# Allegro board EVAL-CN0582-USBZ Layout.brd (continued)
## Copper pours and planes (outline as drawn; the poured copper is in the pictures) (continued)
5V_USB on L3_SIG: 8.51,42.93 8.51,40.77 9.78,40.77 9.78,42.93
26V8_SUPPLY on TOP: 23.75,72.52 24,72.26 26.29,72.26 26.54,72.52 26.54,78.87 26.42,78.99 23.88,78.99 23.75,78.87
26V_SUPPLY on TOP (solid shape): 96.14,60.74 96.14,58.97 96.01,58.85 92.46,58.85 92.33,58.97 92.33,60.74 92.46,60.86 96.01,60.86
26V_SUPPLY on TOP (solid shape): 96.14,22.23 96.14,20.46 96.01,20.34 92.46,20.34 92.33,20.46 92.33,22.23 92.46,22.35 96.01,22.35
26V_SUPPLY on TOP (solid shape): 92.76,68.97 92.81,68.97 93.44,68.97 93.48,68.97 93.53,68.99 96.14,68.99 96.27,68.86 96.27,67.23 96.14,67.1 92.58,67.1 92.46,67.23 92.46,68.86 92.58,68.99 92.71,68.99
26V_SUPPLY on TOP (solid shape): 92.76,30.46 92.81,30.46 93.44,30.46 93.48,30.46 93.53,30.48 96.14,30.48 96.27,30.35 96.27,28.72 96.14,28.59 92.58,28.59 92.46,28.72 92.46,30.35 92.58,30.48 92.71,30.48
26V_SUPPLY on TOP: 32,75.56 32,73.15 31.5,72.64 30.61,72.64 29.34,71.37 27.81,71.37 27.69,71.5 27.69,74.55 27.81,74.68 31.5,74.68 31.75,74.93 31.75,75.56
26V_SUPPLY on L4_SIG: 38.61,79.76 70.1,79.76 70.1,73.91 70.18,73.73 70.36,73.66 106.43,73.66 106.43,10.92 88.9,10.92 88.9,14.48 92.33,14.48 92.51,14.55 92.58,14.73 92.58,31.88 92.51,32.06 92.33,32.13 89.15,32.13 89.15,35.56 92.33,35.56 92.51,35.63 92.58,35.81 92.58,49.28 92.51,49.46 92.33,49.53 89.03,49.53 89.03,53.09 92.33,53.09 92.51,53.16 92.58,53.34 92.58,64.39 92.51,64.57 92.33,64.64 62.99,64.64 62.99,74.42 62.92,74.6 62.74,74.68 45.09,74.68 44.91,74.6 44.83,74.42 44.83,70.99 26.42,70.99 26.42,74.8 38.35,74.8 38.53,74.88 38.61,75.06
DGND on TOP: 33.27,76.83 31.11,76.83 30.99,76.96 29.84,76.96 29.59,77.22 29.59,78.74 26.92,78.74 26.8,78.61 26.8,75.31 26.92,75.18 30.48,75.18 31.11,75.82 33.27,75.82
DGND on TOP: 10.16,45.47 10.03,45.34 6.98,45.34 6.6,44.96 6.6,39.75 6.48,39.62 3.94,39.62 3.81,39.75 3.81,40.51 4.45,41.15 4.45,43.18 4.19,43.43 0.89,43.43 0.89,51.56 1.14,51.82 6.48,51.82 8.26,53.59 10.03,53.59 10.16,53.47
DGND on BOTTOM: 0.76,103.76 118.74,103.76 118.74,0.64 0.76,0.64 ; 5 cut-outs
DGND on L2_GND, L5_GND: 0.76,103.76 118.74,103.76 118.74,0.64 0.76,0.64
DGND on L3_SIG: 0.76,103.76 118.74,103.76 118.74,0.64 0.76,0.64
P5V_SUPPLY on TOP: 53.09,102.36 53.09,99.95 53.21,99.82 55.25,99.82 55.37,99.95 55.37,102.36 55.25,102.49 53.21,102.49
P5V_SUPPLY on L3_SIG: 53.85,102.36 53.85,100.97 55.37,100.97 55.37,102.36
P5V_SUPPLY on L4_SIG: 40.39,103.76 118.74,103.76 118.74,88.9 98.55,88.9 98.55,96.27 98.48,96.45 98.3,96.52 70.48,96.52 70.31,96.45 70.23,96.27 70.23,92.58 70.31,92.4 70.48,92.33 71.37,92.33 71.37,89.53 40.39,89.53
V1P2_SUPPLY on TOP: 29.13,14.99 29.13,14.17 30.3,13 30.3,11.63 30.38,11.56 32.23,11.56 32.31,11.63 32.31,14.35 32.05,14.6 30.1,14.6 29.72,14.99
V1P2_SUPPLY on L4_SIG: 35.16,27.69 50.31,27.69 51.05,26.95 51.05,23.24 51.07,23.14 51.13,23.06 53.09,21.1 53.09,12.81 52.09,11.81 30.73,11.81 30.73,22.61 34.04,22.61 34.22,22.68 34.29,22.86 34.29,26.82
(no net) on TOP: 89.53,59.2 89.53,56.28 89.66,56.15 91.82,56.15 91.95,56.28 91.95,59.07 91.82,59.2
(no net) on TOP: 89.66,80.15 89.66,77.23 89.79,77.1 91.95,77.1 92.08,77.23 92.08,80.03 91.95,80.15
(no net) on TOP: 74.55,74.18 73.41,74.18 73.15,74.44 73.15,77.74 73.28,77.87 74.42,77.87 74.68,77.61 74.68,74.31
(no net) on TOP: 89.66,41.64 89.66,38.72 89.79,38.59 91.95,38.59 92.08,38.72 92.08,41.51 91.95,41.64
(no net) on TOP: outline of 118 points within 0.76,0.63 118.75,103.76 ; 18 cut-outs
(no net) on TOP: 96.27,67.23 96.27,68.86 96.14,68.99 92.58,68.99 92.46,68.86 92.46,67.23 92.58,67.1 96.14,67.1
(no net) on TOP: 96.14,20.46 96.14,22.23 96.01,22.35 92.46,22.35 92.33,22.23 92.33,20.46 92.46,20.34 96.01,20.34
(no net) on TOP: 97.54,66.44 97.54,64.53 97.79,64.28 97.79,63.4 97.66,63.28 93.73,63.28 93.6,63.4 93.6,66.56 97.41,66.56
(no net) on TOP: 74.55,35.67 73.41,35.67 73.15,35.93 73.15,39.23 73.28,39.35 74.42,39.35 74.68,39.1 74.68,35.8
(no net) on TOP: 74.42,53.23 73.28,53.23 73.03,53.48 73.03,56.78 73.15,56.91 74.3,56.91 74.55,56.66 74.55,53.36
(no net) on TOP: 74.42,14.72 73.28,14.72 73.03,14.97 73.03,18.27 73.15,18.4 74.3,18.4 74.55,18.15 74.55,14.84
(no net) on TOP: 97.54,27.92 97.54,26.02 97.79,25.76 97.79,24.89 97.66,24.77 93.73,24.77 93.6,24.89 93.6,28.05 97.41,28.05
(no net) on TOP: 96.14,58.97 96.14,60.74 96.01,60.86 92.46,60.86 92.33,60.74 92.33,58.97 92.46,58.85 96.01,58.85
(no net) on TOP: 97.41,58.18 97.41,56.28 97.66,56.02 97.66,55.15 97.54,55.02 93.6,55.02 93.47,55.15 93.47,58.31 97.28,58.31
(no net) on TOP: 97.41,19.67 97.41,17.76 97.66,17.51 97.66,16.64 97.54,16.51 93.6,16.51 93.47,16.64 93.47,19.8 97.28,19.8
(no net) on TOP: 96.27,28.72 96.27,30.35 96.14,30.48 92.58,30.48 92.46,30.35 92.46,28.72 92.58,28.59 96.14,28.59
(no net) on TOP: 89.53,20.69 89.53,17.76 89.66,17.64 91.82,17.64 91.95,17.76 91.95,20.56 91.82,20.69
3P3V_SUPPLY on TOP: 57.91,29.97 57.91,25.02 57.66,24.77 56.26,24.77 56.01,25.02 56.01,29.85 56.13,29.97
3P3V_SUPPLY on TOP: 17.14,18.41 17.14,18.67 17.4,18.92 17.4,22.48 17.27,22.61 13.08,22.61 12.45,21.97 12.45,18.67 12.7,18.41
3P3V_SUPPLY on L3_SIG: 51.18,20.96 51.18,17.27 47.88,13.97 40.39,13.97 40.13,14.22 40.13,20.45 40.39,20.7 42.29,20.7 44.01,22.42 44.01,26.99 44.45,27.43 49.28,27.43 51.69,25.02 51.69,21.46
3P3V_SUPPLY on L4_SIG: 0.76,103.76 39.88,103.76 39.88,89.28 39.95,89.1 40.13,89.03 69.34,89.03 69.34,80.26 38.35,80.26 38.17,80.19 38.1,80.01 38.1,75.31 31.37,75.31 31.37,87.5 31.35,87.6 31.29,87.68 31.04,87.94 30.96,87.99 30.86,88.01 22.86,88.01 22.76,87.99 22.68,87.94 13.92,79.17 13.86,79.09 13.84,78.99 13.84,36.96 13.08,36.96 12.9,36.88 12.83,36.7 12.83,30.73 12.9,30.55 13.08,30.48 15.77,30.48 18.16,28.09 18.16,18.92 17.14,18.92 16.97,18.85 16.89,18.67 16.89,16 15.62,16 15.44,15.93 15.37,15.75 15.37,13.59 15.44,13.41 15.62,13.33 19.3,13.33 19.48,13.41 19.56,13.59 19.56,14.86 26.16,14.86 26.34,14.93 26.42,15.11 26.42,70.48 45.09,70.48 45.26,70.56 45.34,70.74 45.34,74.17 48.01,74.17 48.01,62.1 42.55,62.1 42.37,62.03 42.29,61.85 42.29,58.42 42.31,58.32 42.37,58.24 44.14,56.46 44.23,56.41 44.32,56.39 62.48,56.39 62.48,43.56 62.56,43.38 62.74,43.31 71.5,43.31 71.5,31.62 59.56,31.62 59.38,31.55 59.31,31.37 59.31,0.64 0.76,0.64 ; 1 cut-out
10P5V_SUPPLY on TOP: 36.83,102.23 36.83,99.69 37.21,99.31 39.88,99.31 39.88,102.23 39.75,102.36 36.96,102.36
-10P5_SUPPLY on TOP: 43.56,90.68 43.56,87.63 43.31,87.38 41.02,87.38 40.77,87.63 40.77,90.68 40.89,90.8 43.43,90.8
CON_VBUS on TOP: 6.73,39.37 6.73,37.46 3.94,37.46 3.81,37.59 3.81,39.37
CON_VBUS on L3_SIG: 3.84,39.27 3.84,29.95 4.22,29.57 10.9,29.57 11.07,29.74 11.07,32.64 10.72,32.99 10.72,39.27 10.62,39.37 3.94,39.37
N5V_SUPPLY on TOP: 53.47,89.74 53.47,87.99 53.54,87.91 55.35,87.91 55.47,88.04 55.47,89.71 55.4,89.79 53.52,89.79
N5V_SUPPLY on BOTTOM: 53.75,95.91 53.75,87.88 54.13,87.5 90.42,87.5 92.08,89.15 102.9,89.15 103.15,89.41 103.15,96.06 99.11,96.06 99.09,96.04 95.1,100.03 57.86,100.03
N5V_SUPPLY on L3_SIG: 101.22,90.68 96.65,90.68 96.27,90.3 96.27,83.19 98.93,80.52 98.93,14.86 99.31,14.48 101.35,14.48 101.47,14.6 101.47,90.42
SYS_POWER on TOP: 29.34,90.93 29.34,84.71 29.46,84.58 31.88,84.58 32.13,84.84 32.13,87.25 31.11,88.27 31.11,88.52 30.73,88.9 30.73,90.93
SYS_POWER on TOP: 16.89,74.17 16.89,69.22 16.64,68.96 13.84,68.96 13.72,69.09 13.72,74.04 13.84,74.17
SYS_POWER on TOP: 22.99,63.25 25.78,63.25 26.04,63.5 26.92,63.5 26.92,64.64 25.02,64.64 24.64,64.26 22.99,64.26
SYS_POWER on TOP: 16,16.51 16,14.73 16.13,14.6 18.92,14.6 19.18,14.86 19.18,16.64 16.13,16.64
SYS_POWER on TOP: 18.54,77.22 18.29,77.22 18.29,78.87 18.03,79.12 18.03,80.52 18.16,80.64 19.18,80.64 19.3,80.52 19.3,78.99 18.54,78.23
SYS_POWER on TOP: 21.72,42.16 21.72,38.99 24.51,38.99 25.02,39.5 25.02,41.66 24.51,42.16
SYS_POWER on L4_SIG: 22.97,87.5 30.76,87.5 30.86,87.4 30.86,75.31 26.16,75.31 25.98,75.24 25.91,75.06 25.91,15.37 19.3,15.37 19.12,15.29 19.05,15.11 19.05,13.84 15.88,13.84 15.88,15.49 17.14,15.49 17.32,15.57 17.4,15.75 17.4,18.41 18.41,18.41 18.59,18.49 18.67,18.67 18.67,28.19 18.65,28.29 18.59,28.37 16.05,30.91 15.97,30.97 15.88,30.99 13.34,30.99 13.34,36.45 14.1,36.45 14.28,36.52 14.35,36.7 14.35,78.89
UNNAMED_22_ADP5071V2_I1_INBK on TOP: 29.97,95.88 29.97,96.9 28.32,98.55 28.32,101.98 28.45,102.11 29.84,102.11 29.97,101.98 29.97,97.66 30.35,97.28 30.35,95.88
UNNAMED_22_ADP5071V2_I1_SW1 on TOP: 30.61,95.63 30.61,101.85 30.86,102.11 34.8,102.11 34.8,98.17 34.42,97.79 31.5,97.79 31.11,97.41 31.11,95.63
UNNAMED_22_ADP5071V2_I1_SW2 on TOP: 31.24,91.06 31.24,89.15 31.75,88.65 38.35,88.65 38.61,88.9 38.61,90.55 38.1,91.06
UNNAMED_22_ADP7118V2_I56_VIN on TOP: 47.75,99.82 43.82,99.82 43.69,99.69 42.04,99.69 41.78,99.44 40.51,99.44 40.51,102.36 40.64,102.49 47.62,102.49 47.75,102.36
UNNAMED_22_ADP7118V2_I56_VOUT on TOP: 48.39,102.36 48.39,99.95 48.51,99.82 52.45,99.82 52.58,99.95 52.58,102.23 52.32,102.49 48.51,102.49
UNNAMED_22_ADP7182V5_I66_EPAD on TOP: 48.01,90.68 44.45,90.68 44.32,90.55 44.32,87.76 44.45,87.63 47.62,87.63 47.75,87.76 47.75,89.53 47.88,89.66 49.15,89.66 49.28,89.79 49.28,93.85 49.02,94.11 48.26,94.11 48.13,93.98 48.13,90.8
UNNAMED_22_ADP7182V5_I66_VOUT on TOP: 49.66,90.68 49.66,90.42 49.78,90.42 49.91,90.3 49.91,87 50.16,86.74 52.58,86.74 52.96,87.12 52.96,90.55 52.83,90.68
UNNAMED_22_CAP_I337_N1 on TOP: 0.89,42.93 3.94,42.93 3.94,41.4 3.3,40.77 3.3,36.32 3.05,36.07 2.67,36.07 2.67,28.32 2.92,28.07 8.13,28.07 8.13,25.53 7.75,25.15 0.89,25.15 0.76,25.27 0.76,42.8
UNNAMED_22_CAP_I337_N1 on BOTTOM: 0.89,38.35 9.53,38.35 9.53,26.42 0.89,26.42
UNNAMED_23_ADP1708_I291_OUT on TOP: 14.35,17.91 14.35,16.38 13.97,16 13.97,14.6 13.08,14.6 12.57,14.1 11.43,14.1 11.18,14.35 11.18,17.53 11.56,17.91
UNNAMED_23_ADP7118V2_I83_EN on TOP: 31.88,64.77 31.88,60.2 31.24,59.56 29.08,59.56 28.83,59.31 28.83,58.29 29.21,57.91 33.02,57.91 33.02,58.42 34.16,59.56 34.16,64.64 34.04,64.77
UNNAMED_23_ADP7118V2_I83_VOUT on TOP: 33.91,58.8 33.91,57.91 34.04,57.78 37.08,57.78 37.21,57.66 38.23,57.66 38.23,58.42 38.1,58.55 37.47,58.55 37.08,58.93 34.04,58.93
UNNAMED_23_ADP7142_I123_EN on TOP: 32,77.09 31.62,77.09 31.24,77.47 30.23,77.47 30.1,77.6 30.1,79.12 29.84,79.38 23.75,79.38 23.49,79.63 23.49,80.64 23.62,80.77 31.62,80.77 32,80.39
UNNAMED_23_CAP_I54_N1 on TOP: 18.59,64.24 18.59,63.22 15.49,63.22 15.01,62.74 11.15,62.74 11.1,62.79 11.1,64.08 11.25,64.24
UNNAMED_23_CAP_I54_N2 on TOP: 18.59,62.92 15.8,62.92 15.75,62.86 15.75,62.31 17.07,62.31 17.32,62.56 18.59,62.56
UNNAMED_23_CAP_I55_N1 on TOP: 18.59,65.18 17.14,65.18 16.84,65.48 11.15,65.48 11.13,65.46 11.13,66.75 11.2,66.83 16.43,66.83 17.09,66.17 18.59,66.17
UNNAMED_23_CAP_I55_N2 on TOP: 18.54,64.52 15.82,64.52 15.82,65.1 16.81,65.1 17.04,64.87 18.57,64.87 18.57,64.54
UNNAMED_23_CAP_I63_N2 on TOP: 22.99,65.79 24.64,65.79 25.15,65.28 33.4,65.28 33.4,66.8 33.27,66.93 25.27,66.93 24.51,66.17 22.99,66.17
UNNAMED_23_CAP_I241_N2 on TOP: 13.72,56.01 13.72,54.61 13.84,54.48 14.48,54.48 14.48,50.55 13.59,49.66 13.59,47.62 10.92,47.62 10.67,47.88 10.67,53.09 10.92,53.34 10.92,56.64 10.67,56.9 10.67,58.93 13.08,58.93 13.08,58.17 12.57,57.66 12.57,56.39 12.83,56.13 13.59,56.13
UNNAMED_23_CAP_I249_N2 on TOP: 18.41,48.64 18.41,47.62 20.95,47.62 20.95,48.64
UNNAMED_23_CAP_I249_N2 on TOP: 21.21,42.16 21.34,42.04 21.34,39.62 21.21,39.5 20.7,39.5 18.54,37.34 18.54,35.18 16,35.18 15.75,35.43 14.61,35.43 14.61,36.2 15.62,36.2 16,36.58 16,37.72 16.89,38.61 16.89,42.04 17.02,42.16
UNNAMED_23_CAP_I249_N2 on TOP: 18.54,44.7 18.54,43.94 20.7,43.94 20.83,44.07 20.83,44.7 20.7,44.83 18.67,44.83
UNNAMED_23_CAP_I249_N2 on L3_SIG: 19.43,48.51 20.95,48.51 21.34,48.13 21.34,39.62 21.21,39.5 19.43,39.5 19.18,39.75 19.18,48.26
UNNAMED_23_CAP_I257_N1 on TOP: 14.61,45.97 14.61,44.83 15.88,44.83 16.13,44.58 17.91,44.58 18.29,44.96 21.59,44.96 21.72,45.09 21.72,45.97 21.59,46.1 14.73,46.1
UNNAMED_23_CAP_I257_N2 on TOP: 14.61,43.81 15.88,43.81 16.13,44.07 17.91,44.07 18.29,43.69 21.59,43.69 21.97,44.07 21.97,44.83 22.1,44.96 22.86,44.96 22.99,45.09 23.62,45.09 23.75,44.96 23.75,44.32 22.73,44.32 22.73,42.67 22.61,42.54 14.73,42.54 14.61,42.67
UNNAMED_23_CAP_I260_N1 on TOP: 14.61,50.16 14.61,48.64 15.88,48.64 16.13,48.39 17.78,48.39 18.16,48.77 21.34,48.77 21.34,50.67 21.21,50.8 15.24,50.8
UNNAMED_23_CAP_I260_N2 on TOP: 14.61,47.62 15.75,47.62 16,47.88 17.78,47.88 18.16,47.5 21.34,47.5 21.72,47.88 21.72,49.78 22.86,49.78 22.86,47.12 22.1,46.35 14.73,46.35 14.61,46.48
UNNAMED_23_CN2P_I240_N1 on TOP: 2.03,57.15 2.03,52.83 2.54,52.32 6.1,52.32 8.13,54.36 10.29,54.36 10.29,57.28 10.16,57.4 2.29,57.4
UNNAMED_23_DIOSCHOTTKY_I115_P on TOP: 18.29,76.07 18.29,74.68 18.54,74.42 18.54,69.09 18.67,68.96 22.73,68.96 22.86,69.09 22.86,73.79 22.42,74.23 21.02,74.23 19.18,76.07
UNNAMED_23_RES_I296_N2 on TOP: 21.97,45.34 21.97,45.97 22.48,45.97 23.24,46.74 23.24,55.24 22.48,56.01 20.45,56.01 20.45,57.15 23.88,57.15 24.51,56.52 24.51,45.85 24.13,45.47 22.73,45.47 22.61,45.34
UNNAMED_23_RES_I302_N1 on TOP: 14.61,59.31 14.61,58.29 14.99,57.91 15.49,57.91 15.49,57.02 13.97,57.02 13.72,56.77 12.95,56.77 12.95,57.4 13.84,58.29 13.84,59.31
UNNAMED_24_CAP_I12_N2 on TOP (solid shape): 97.54,66.44 97.54,64.53 97.79,64.28 97.79,63.4 97.66,63.28 93.73,63.28 93.6,63.4 93.6,65.94 95.01,65.94 95.01,64.87 95.01,64.85 95.02,64.81 95.03,64.78 95.06,64.74 95.09,64.71 95.12,64.69 95.16,64.68 95.19,64.67 95.21,64.67 95.62,64.67 95.64,64.67 95.68,64.68 95.72,64.69 95.75,64.71 95.78,64.74 95.8,64.78 95.82,64.81 95.82,64.85 95.82,64.87 95.82,65.94 95.82,65.96 95.82,66 95.8,66.04 95.78,66.07 95.75,66.1 95.72,66.12 95.68,66.13 95.64,66.14 95.62,66.14 95.21,66.14 95.19,66.14 95.16,66.13 95.12,66.12 95.09,66.1 95.06,66.07 95.03,66.04 95.02,66 95.01,65.96 95.01,65.94 93.6,65.94 93.6,66.56 97.41,66.56
UNNAMED_24_CAP_I80_N2 on TOP (solid shape): 97.41,58.18 97.41,56.28 97.66,56.02 97.66,55.15 97.54,55.02 95.57,55.02 95.55,55.04 95.51,55.08 95.46,55.11 95.41,55.14 95.35,55.16 95.29,55.17 95.23,55.17 95.18,55.17 95.12,55.16 95.06,55.14 95.01,55.11 94.96,55.08 94.91,55.04 94.89,55.02 93.6,55.02 93.47,55.15 93.47,57.68 94.88,57.68 94.88,56.62 94.88,56.6 94.89,56.56 94.91,56.52 94.93,56.49 94.96,56.46 94.99,56.44 95.03,56.42 95.07,56.41 95.09,56.41 95.49,56.41 95.51,56.41 95.55,56.42 95.59,56.44 95.62,56.46 95.65,56.49 95.67,56.52 95.69,56.56 95.7,56.6 95.7,56.62 95.7,57.68 95.7,57.7 95.69,57.74 95.67,57.78 95.65,57.81 95.62,57.84 95.59,57.86 95.55,57.88 95.51,57.89 95.49,57.89 95.09,57.89 95.07,57.89 95.03,57.88 94.99,57.86 94.96,57.84 94.93,57.81 94.91,57.78 94.89,57.74 94.88,57.7 94.88,57.68 93.47,57.68 93.47,58.31 97.28,58.31
UNNAMED_25_CAP_I24_N2 on TOP (solid shape): 97.41,19.67 97.41,17.76 97.66,17.51 97.66,16.64 97.54,16.51 95.57,16.51 95.55,16.53 95.51,16.57 95.46,16.6 95.41,16.63 95.35,16.65 95.29,16.66 95.23,16.66 95.18,16.66 95.12,16.65 95.06,16.63 95.01,16.6 94.96,16.57 94.91,16.53 94.89,16.51 93.6,16.51 93.47,16.64 93.47,19.17 94.88,19.17 94.88,18.11 94.88,18.09 94.89,18.05 94.91,18.01 94.93,17.98 94.96,17.95 94.99,17.93 95.03,17.91 95.07,17.9 95.09,17.9 95.49,17.9 95.51,17.9 95.55,17.91 95.59,17.93 95.62,17.95 95.65,17.98 95.67,18.01 95.69,18.05 95.7,18.09 95.7,18.11 95.7,19.17 95.7,19.19 95.69,19.23 95.67,19.27 95.65,19.3 95.62,19.33 95.59,19.35 95.55,19.37 95.51,19.38 95.49,19.38 95.09,19.38 95.07,19.38 95.03,19.37 94.99,19.35 94.96,19.33 94.93,19.3 94.91,19.27 94.89,19.23 94.88,19.19 94.88,19.17 93.47,19.17 93.47,19.8 97.28,19.8
UNNAMED_25_CAP_I44_N2 on TOP (solid shape): 97.54,27.92 97.54,26.02 97.79,25.76 97.79,24.89 97.66,24.77 93.73,24.77 93.6,24.89 93.6,27.43 95.01,27.43 95.01,26.36 95.01,26.34 95.02,26.3 95.03,26.26 95.06,26.23 95.09,26.2 95.12,26.18 95.16,26.17 95.19,26.16 95.21,26.16 95.62,26.16 95.64,26.16 95.68,26.17 95.72,26.18 95.75,26.2 95.78,26.23 95.8,26.26 95.82,26.3 95.82,26.34 95.82,26.36 95.82,27.43 95.82,27.45 95.82,27.49 95.8,27.52 95.78,27.56 95.75,27.59 95.72,27.61 95.68,27.62 95.64,27.63 95.62,27.63 95.21,27.63 95.19,27.63 95.16,27.62 95.12,27.61 95.09,27.59 95.06,27.56 95.03,27.52 95.02,27.49 95.01,27.45 95.01,27.43 93.6,27.43 93.6,28.05 97.41,28.05
UNNAMED_28_ADA48071_I307__1 on TOP: 60.58,59.89 62.05,59.89 62.13,59.97 65.02,59.97 65.07,59.92 65.07,61.52 65,61.59 60.68,61.59 60.55,61.47 60.55,59.92
UNNAMED_29_ADP1708_I198_IN on TOP: 27.05,14.86 27.05,13.97 26.42,13.33 26.42,11.68 26.29,11.56 24.89,11.56 24.76,11.68 24.76,13.59 25.02,13.84 25.02,14.86 25.15,14.99 26.92,14.99

Small or netless copper shapes (teardrops, artwork), in the pictures only: 1 on L3_SIG

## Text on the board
User.Comments: 5.    BOARDS TO BE SHIPPED SINGULATED AFTER ASSEMBLY PROCESS | 7.    SET S1 1A -1B AS ON AND SET 2A-2B AS OFF. | 6.    SMOOTHEN EDGES AND FREE FROM BURS AFTER DEPANELIZATION PROCESS | 8.    SHIP STAND OFF (M032310) AND SCREW (M035074) TOGETHER WITH ASSEMBLED BOARD | CHAMFER | FOR COMPONENT Y1 | BOTTOM VIEW | TOP VIEW | DETAIL A | 1 | 4 | 2 | 3 | FOR COMPONENT Y2,Y3,Y4 AND Y5 | DETAIL B | ON | OFF
Ref Des/Assembly Top: 1
Ref Des/Silkscreen Top: C | 5VIN | A | CS | 3V3 | SDA | SCL | GND | CLK | MOSI | MISO | INT1 | BUSY | INT2 | ON | OFF | SPI MODE | USB MODE | ORTIG | OCLK | OGND | ICKL | ITRIG | IGND | 3.3V | EVAL-CN0582-USBZ
PAGE_OUTLINE: B | C | D | ECR-104761 | ECR-108062 | ECR-108988 | 21DEC21 | 04APR22 | 06JUL22 | K. CALIP | J. SATSATIN | CUSTOMER EVAL BOARD Z
DIMENSION: " " | (REF) | DIA MAX | +2/-0 MILS
User.11: C | A | SEE DETAIL A | SEE DETAIL B | WIRE ENTRY
User.15: 15.    BOARDS TO BE SHIPPED IN ARRAYS. | PANEL TO BE SUBJECTED TO CUSTOMER'S APPROVAL | PANELED SOLDER PASTE STENCIL SHOULD BE SENT TO THE CUSTOMER | LAYER | L1 | L3 | 90 OHMS DP | IMPEDANCE | NOTE: ALL IMPEDANCE TOLERANCE +/-10% | DP = DIFFERENTIAL PAIR | REFERENCE | L2/L4 | L2 | LINE WIDTH | 6MILS | SPACE | 10MILS | IMPEDANCE TABLE
User.23: 08-      -07 | L2 GND
User.24: 08-      -08 | L3 SIG
User.25: L4 SIG | 08-      -09
User.26: L5 GND | 08-      -10
User.45: FIGURE | SIZE | 8.0 | 10.0 | 35.0 | 40.0 | 45.0 | 50.0 | 65.0 | 80.0 | 26.0 | 39.0 | 51.0 | 94.0 | 125.0 | 44.0x20.0 | 37.0x26.0 | PLATED | NON-PLATED | DRILL CHART: TOP to BOTTOM | ALL UNITS ARE IN MILS | QTY | 79 | 2180 | 2 | 34 | 8 | 20 | 1 | 3 | 4 | TOLERANCE/NOTES
